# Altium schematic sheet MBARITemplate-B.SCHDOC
size B; Organization: Monterey Bay Aquarium Research Institute; Address1: 7700 Sandholdt Rd; Address2: Moss Landing, CA 95039-9644; CompanyName: MBARI
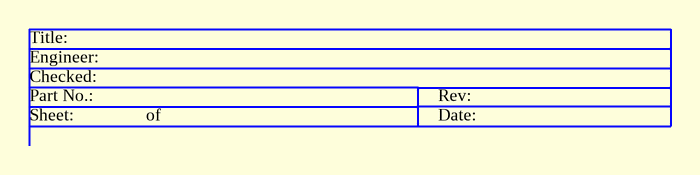
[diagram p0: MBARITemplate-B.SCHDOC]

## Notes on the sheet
- Sheet:
- Title:
- Engineer:
- Part No.:
- Checked:
- of
- Rev:
- Date:
